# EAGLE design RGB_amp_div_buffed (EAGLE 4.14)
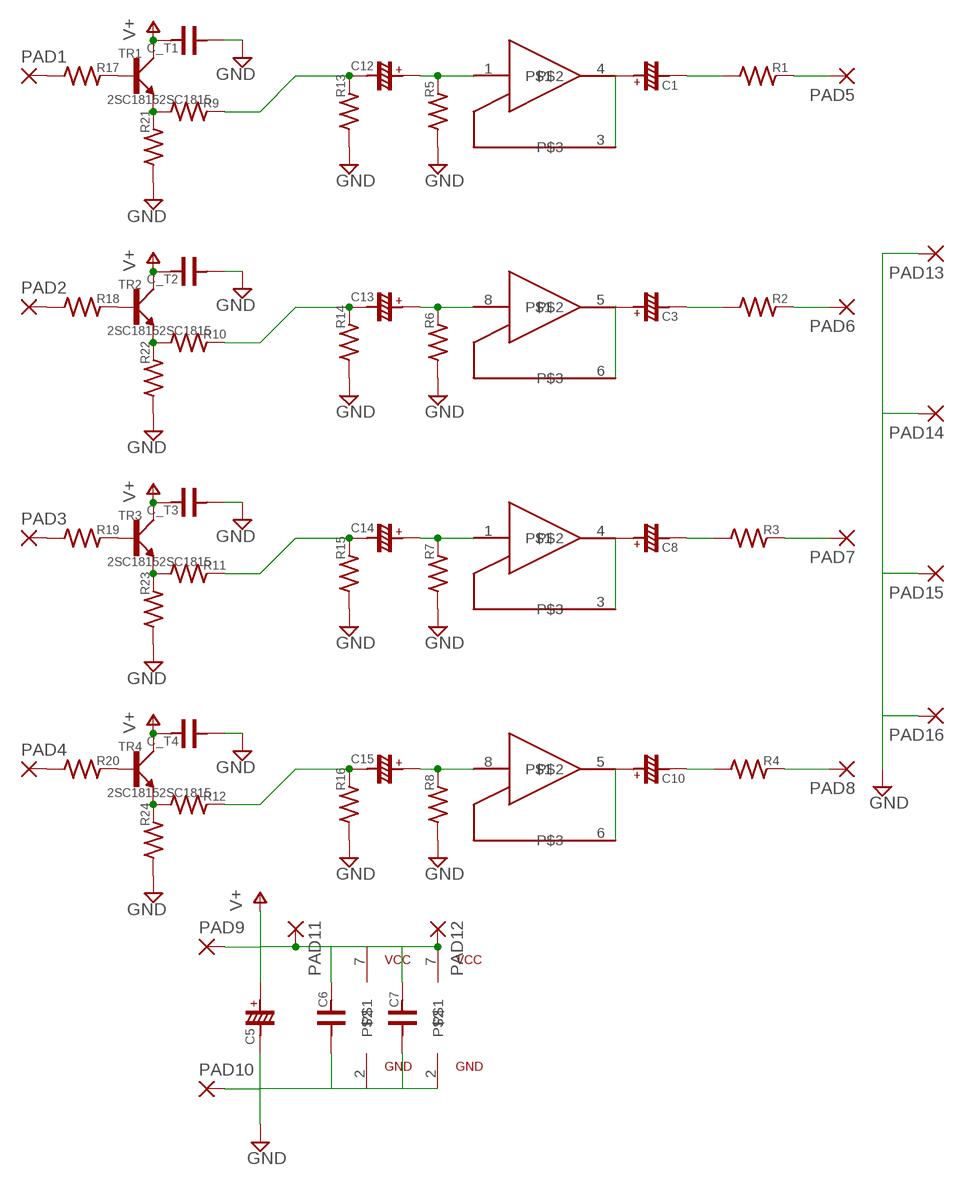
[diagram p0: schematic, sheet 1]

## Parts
C1  POLCD8  [TT2D8]
C3  POLCD8  [TT2D8]
C5  POLCV  [TT2D5]
C6  C0805  [R0805]
C7  C0805  [R0805]
C8  POLCD8  [TT2D8]
C10  POLCD8  [TT2D8]
C12  POLCV  [TT2D5]
C13  POLCV  [TT2D5]
C14  POLCV  [TT2D5]
C15  POLCV  [TT2D5]
C_T1  C0805  [R0805]
C_T2  C0805  [R0805]
C_T3  C0805  [R0805]
C_T4  C0805  [R0805]
IC1  NJM2267  [NJM2267]
IC2  NJM2267  [NJM2267]
PAD1  PAD2.15/0.9  [2.15/0.9]
PAD2  PAD2.15/0.9  [2.15/0.9]
PAD3  PAD2.15/0.9  [2.15/0.9]
PAD4  PAD2.15/0.9  [2.15/0.9]
PAD5  PAD2.15/0.9  [2.15/0.9]
PAD6  PAD2.15/0.9  [2.15/0.9]
PAD7  PAD2.15/0.9  [2.15/0.9]
PAD8  PAD2.15/0.9  [2.15/0.9]
PAD9  PAD2.5/0.9  [2,54/0,9]
PAD10  PAD2.5/0.9  [2,54/0,9]
PAD11  PAD2.15/0.9  [2.15/0.9]
PAD12  PAD2.15/0.9  [2.15/0.9]
PAD13  PAD2.15/0.9  [2.15/0.9]
PAD14  PAD2.15/0.9  [2.15/0.9]
PAD15  PAD2.15/0.9  [2.15/0.9]
PAD16  PAD2.15/0.9  [2.15/0.9]
R1  RR_100MIL  [0204/2.5]
R2  RR_100MIL  [0204/2.5]
R3  RR_100MIL  [0204/2.5]
R4  RR_100MIL  [0204/2.5]
R5  RR3216  [R1206]
R6  RR3216  [R1206]
R7  RR3216  [R1206]
R8  RR3216  [R1206]
R9  RR_200MIL  [0204/5]
R10  RR_200MIL  [0204/5]
R11  RR_200MIL  [0204/5]
R12  RR_200MIL  [0204/5]
R13  RR_100MIL  [0204/2.5]
R14  RR_100MIL  [0204/2.5]
R15  RR_100MIL  [0204/2.5]
R16  RR_100MIL  [0204/2.5]
R17  RR_100MIL  [0204/2.5]
R18  RR_100MIL  [0204/2.5]
R19  RR_100MIL  [0204/2.5]
R20  RR_100MIL  [0204/2.5]
R21  RR_100MIL  [0204/2.5]
R22  RR_100MIL  [0204/2.5]
R23  RR_100MIL  [0204/2.5]
R24  RR_100MIL  [0204/2.5]
TR1  2SC18152SC1815  [TO92-]
TR2  2SC18152SC1815  [TO92-]
TR3  2SC18152SC1815  [TO92-]
TR4  2SC18152SC1815  [TO92-]

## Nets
GND: C5.P$2 C6.1 C7.1 C_T1.1 C_T2.1 C_T3.1 C_T4.1 IC1.2 IC2.2 PAD10.1(P) PAD13.1(P) PAD14.1(P) PAD15.1(P) PAD16.1(P) R5.1 R6.1 R7.1 R8.1 R13.1 R14.1 R15.1 R16.1 R21.1 R22.1 R23.1 R24.1
N$1: C1.P$1 IC1.3 IC1.4
N$2: C12.P$2 R9.2 R13.2
N$3: C3.P$1 IC1.5 IC1.6
N$4: C13.P$2 R10.2 R14.2
N$5: C1.P$2 R1.1
N$6: C3.P$2 R2.1
N$7: PAD5.1(P) R1.2
N$8: PAD6.1(P) R2.2
N$9: C14.P$2 R11.2 R15.2
N$10: C12.P$1 IC1.1 R5.2
N$11: C8.P$1 IC2.3 IC2.4
N$12: C15.P$2 R12.2 R16.2
N$14: C10.P$1 IC2.5 IC2.6
N$15: C8.P$2 R3.1
N$16: C10.P$2 R4.1
N$17: PAD7.1(P) R3.2
N$18: PAD8.1(P) R4.2
N$19: PAD1.1(P) R17.1
N$20: C13.P$1 IC1.8 R6.2
N$21: R17.2 TR1.1
N$22: PAD2.1(P) R18.1
N$23: R18.2 TR2.1
N$24: PAD3.1(P) R19.1
N$25: C14.P$1 IC2.1 R7.2
N$26: R19.2 TR3.1
N$27: C15.P$1 IC2.8 R8.2
N$28: PAD4.1(P) R20.1
N$29: R20.2 TR4.1
N$30: R9.1 R21.2 TR1.3
N$31: R10.1 R22.2 TR2.3
N$33: R11.1 R23.2 TR3.3
N$34: R12.1 R24.2 TR4.3
V+: C5.P$1 C6.2 C7.2 C_T1.2 C_T2.2 C_T3.2 C_T4.2 IC1.7 IC2.7 PAD9.1(P) PAD11.1(P) PAD12.1(P) TR1.2 TR2.2 TR3.2 TR4.2

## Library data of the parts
C1 C3 C5 C8 C10 C12-C15 = jikken:POLC
C6 C7 C_T1-C_T4 = jikken:C
IC1 IC2 = jikken:NJM2267
PAD1-PAD16 = jikken:PAD: THROUGH-HOLE PAD
R1-R24 = jikken:R
TR1-TR4 = jikken:2SC1815

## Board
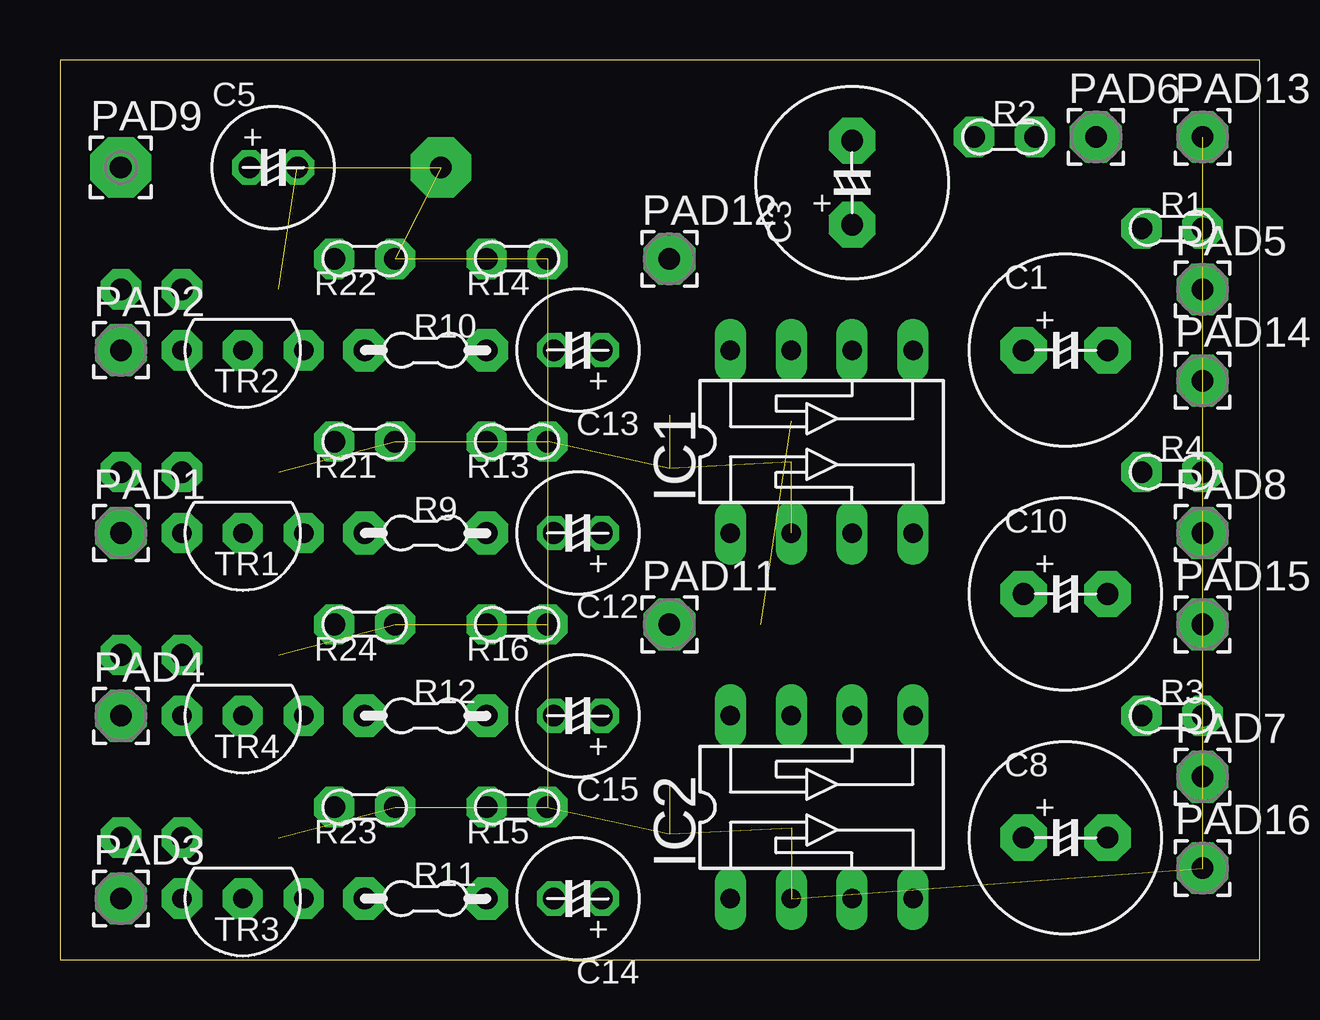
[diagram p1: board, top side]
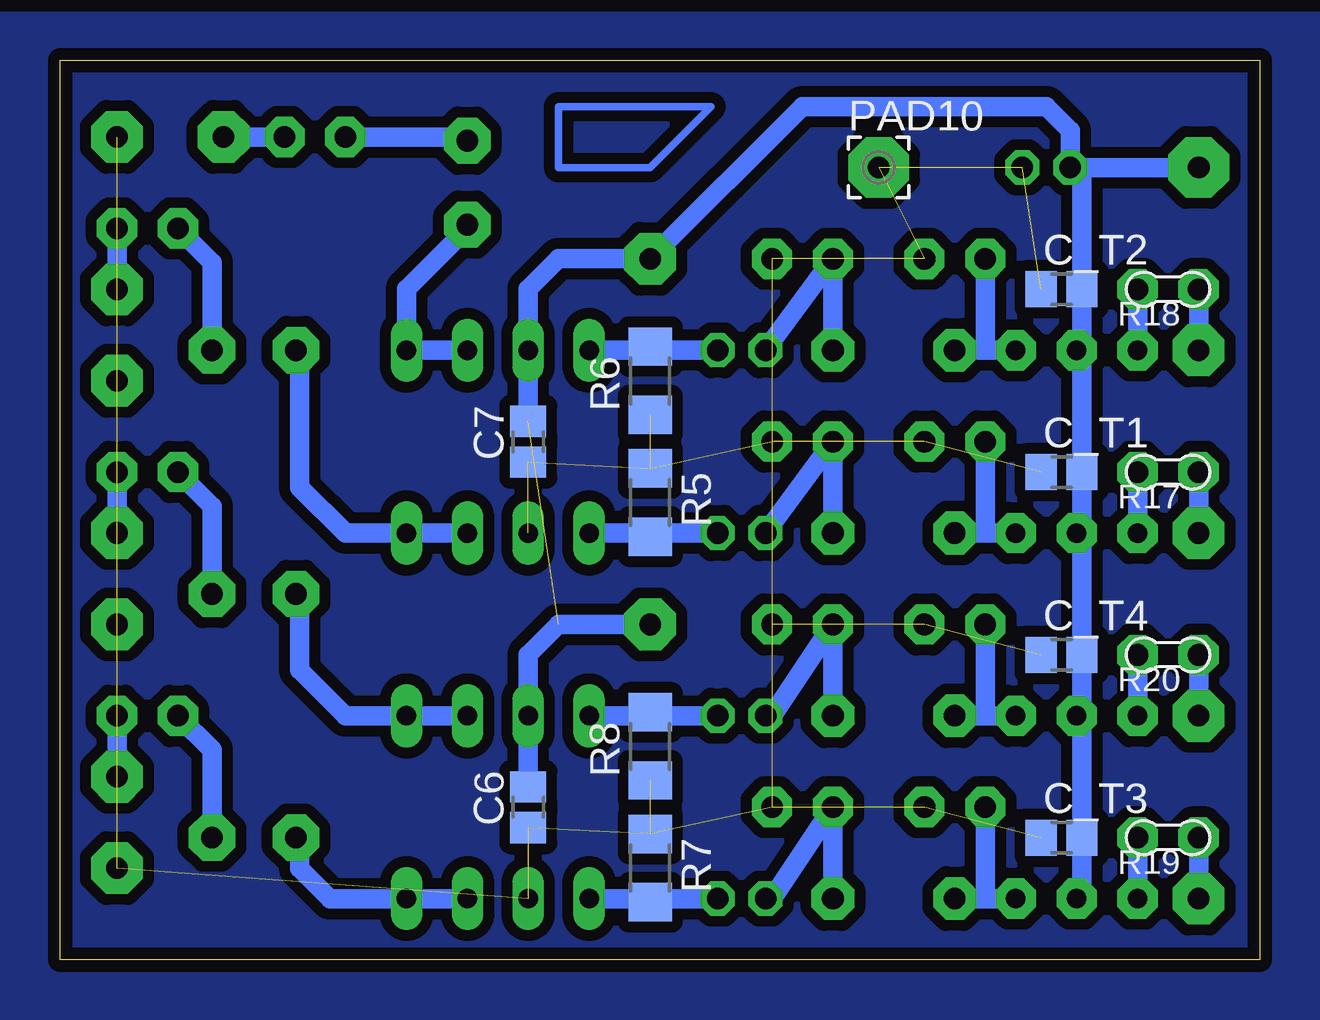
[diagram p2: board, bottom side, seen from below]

Size 50 x 37.5 mm. Coordinates in mm from the lower left corner, seen from the top.
Outline: 0,0 50,0 50,37.5 0,37.5 0,0
Copper layers (1*16): Top 0.035mm / dielectric 1.5mm / Bottom 0.035mm
Design rules "default": minimum track width 10mil, minimum drill 24mil, track to track 18mil, track to pad 18mil, pad to pad 18mil, via to via 18mil, smd to smd 8mil, copper to edge 20mil, drill to drill 8mil, minimum pad ring 10mil, minimum via ring 8mil, stop-mask expansion 4mil, vias tented up to drill 0mil, thermal gap 18mil

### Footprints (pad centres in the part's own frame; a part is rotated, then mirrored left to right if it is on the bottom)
TT2D8 = drill 0.9 pad 1.93 octagon: P$1 -1.75,0; P$2 1.75,0
TT2D5 = drill 0.9 pad 1.422 octagon: P$1 -1,0; P$2 1,0
R0805 = smd 1.3 x 1.5: 1 -0.85,0; 2 0.85,0
NJM2267 = drill 0.813 long: 1 -3.81,-3.81; 2 -1.27,-3.81; 3 1.27,-3.81; 4 3.81,-3.81; 5 3.81,3.81; 6 1.27,3.81; 7 -1.27,3.81; 8 -3.81,3.81
2.15/0.9 = drill 0.9 pad 2.159 octagon: 1 0,0
2,54/0,9 = drill 0.914 pad 2.54 octagon: 1 0,0
0204/2.5 = drill 0.9 pad 1.676 octagon: 1 -1.27,0; 2 1.27,0
R1206 = smd 1.6 x 1.803: 1 -1.422,0; 2 1.422,0
0204/5 = drill 0.9 pad 1.778 octagon: 1 -2.54,0; 2 2.54,0
TO92- = drill 0.813 pad 1.676 octagon: 1 2.54,0; 2 0,0; 3 -2.54,0

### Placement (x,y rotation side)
C1  41.91,25.4 0 top
C3  33.02,32.38 90 top
C5  8.89,33.02 0 top
C6  30.48,6.35 90 bottom
C7  30.48,21.59 90 bottom
C8  41.91,5.08 0 top
C10  41.91,15.24 0 top
C12  21.59,17.78 180 top
C13  21.59,25.4 180 top
C14  21.59,2.54 180 top
C15  21.59,10.16 180 top
C_T1  8.26,20.32 0 bottom
C_T2  8.26,27.94 0 bottom
C_T3  8.26,5.08 0 bottom
C_T4  8.26,12.7 0 bottom
IC1  31.75,21.59 0 top
IC2  31.75,6.35 0 top
PAD1  2.54,17.78 0 top
PAD2  2.54,25.4 0 top
PAD3  2.54,2.54 0 top
PAD4  2.54,10.16 0 top
PAD5  47.62,27.94 0 top
PAD6  43.18,34.29 0 top
PAD7  47.62,7.62 0 top
PAD8  47.62,17.78 0 top
PAD9  2.54,33.02 0 top
PAD10  15.88,33.02 0 bottom
PAD11  25.4,13.97 0 top
PAD12  25.4,29.21 0 top
PAD13  47.62,34.29 0 top
PAD14  47.62,24.13 0 top
PAD15  47.62,13.97 0 top
PAD16  47.62,3.81 0 top
R1  46.35,30.48 0 top
R2  39.37,34.29 0 top
R3  46.35,10.16 0 top
R4  46.35,20.32 0 top
R5  25.4,19.05 270 bottom
R6  25.4,24.13 90 bottom
R7  25.4,3.81 270 bottom
R8  25.4,8.89 90 bottom
R9  15.24,17.78 0 top
R10  15.24,25.4 0 top
R11  15.24,2.54 0 top
R12  15.24,10.16 0 top
R13  19.05,21.59 180 top
R14  19.05,29.21 180 top
R15  19.05,6.35 180 top
R16  19.05,13.97 180 top
R17  3.81,20.32 180 bottom
R18  3.81,27.94 180 bottom
R19  3.81,5.08 180 bottom
R20  3.81,12.7 180 bottom
R21  12.7,21.59 180 top
R22  12.7,29.21 180 top
R23  12.7,6.35 180 top
R24  12.7,13.97 180 top
TR1  7.62,17.78 180 top
TR2  7.62,25.4 180 top
TR3  7.62,2.54 180 top
TR4  7.62,10.16 180 top

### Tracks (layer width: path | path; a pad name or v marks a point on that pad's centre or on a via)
AGND
  pour Bottom: -4.45,39.37 -4.45,-2.54 53.34,-2.54 53.34,39.37
GND  (25 unrouted)
N$1
  Bottom 0.813: IC1.3 IC1.4 38.1,17.78 40.01,19.68 40.01,25.4 C1.P$1
N$2
  Bottom 0.813: R9.2 R13.2 C12.P$2
N$3
  Bottom 0.813: IC1.6 IC1.5 35.56,27.94 33.02,30.48 C3.P$1
N$4
  Bottom 0.813: R10.2 R14.2 C13.P$2
N$5
  Bottom 0.813: C1.P$2 43.66,29.05 R1.1
N$6
  Bottom 0.813: C3.P$2 33.02,34.29 R2.1
N$7
  Bottom 0.813: PAD5.1 R1.2
N$8
  Bottom 0.813: R2.2 PAD6.1
N$9
  Bottom 0.813: R11.2 R15.2 20.32,2.54 C14.P$2
N$10
  Bottom 0.813: 25.4,17.78 IC1.1 | 25.4,17.78 R5.2 | C12.P$1 25.4,17.78
N$11
  Bottom 0.813: IC2.3 IC2.4 38.73,2.54 40.01,3.81 40.01,5.08 C8.P$1
N$12
  Bottom 0.813: R12.2 R16.2 20.32,10.16 C15.P$2
N$14
  Bottom 0.813: IC2.6 IC2.5 38.1,10.16 40.01,12.06 40.01,15.24 C10.P$1
N$15
  Bottom 0.813: C8.P$2 43.66,8.73 R3.1
N$16
  Bottom 0.813: C10.P$2 43.66,18.89 R4.1
N$17
  Bottom 0.813: PAD7.1 R3.2
N$18
  Bottom 0.813: PAD8.1 R4.2
N$19
  Bottom 0.813: PAD1.1 R17.1
N$20
  Bottom 0.813: 25.4,25.4 IC1.8 | 25.4,25.4 R6.2 | C13.P$1 25.4,25.4
N$21
  Bottom 0.813: TR1.1 R17.2
N$22
  Bottom 0.813: PAD2.1 R18.1
N$23
  Bottom 0.813: TR2.1 R18.2
N$24
  Bottom 0.813: PAD3.1 R19.1
N$25
  Bottom 0.813: C14.P$1 25.4,2.54 | 25.4,2.54 R7.2 | 25.4,2.54 IC2.1
N$26
  Bottom 0.813: TR3.1 R19.2
N$27
  Bottom 0.813: 25.4,10.16 IC2.8 | 25.4,10.16 R8.2 | C15.P$1 25.4,10.16
N$28
  Bottom 0.813: PAD4.1 R20.1
N$29
  Bottom 0.813: TR4.1 R20.2
N$30
  Bottom 0.813: TR1.3 11.43,17.78 | 11.43,17.78 R9.1 | 11.43,17.78 R21.2
N$31
  Bottom 0.813: TR2.3 11.43,25.4 | 11.43,25.4 R10.1 | 11.43,25.4 R22.2
N$32
  Bottom 0.305: 22.86,35.56 25.4,33.02 29.21,33.02 29.21,35.56 22.86,35.56
N$33
  Bottom 0.813: TR3.3 11.43,2.54 | 11.43,2.54 R11.1 | 11.43,2.54 R23.2
N$34
  Bottom 0.813: TR4.3 11.43,10.16 | 11.43,10.16 R12.1 | 11.43,10.16 R24.2
V+  (1 unrouted)
  Bottom 0.813: C7.2 IC1.7 30.48,27.94 29.21,29.21 PAD12.1 19.05,35.56 8.89,35.56 7.89,34.56 C5.P$1 7.62,33.02 | C6.2 IC2.7 30.48,12.7 29.21,13.97 PAD11.1 | TR3.2 7.41,2.75 C_T3.2 7.41,9.95 TR4.2 7.41,10.38 C_T4.2 7.41,17.57 TR1.2 7.41,18 C_T1.2 7.41,25.18 TR2.2 7.41,25.61 C_T2.2 7.41,32.8 7.62,33.02 | PAD9.1 7.62,33.02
